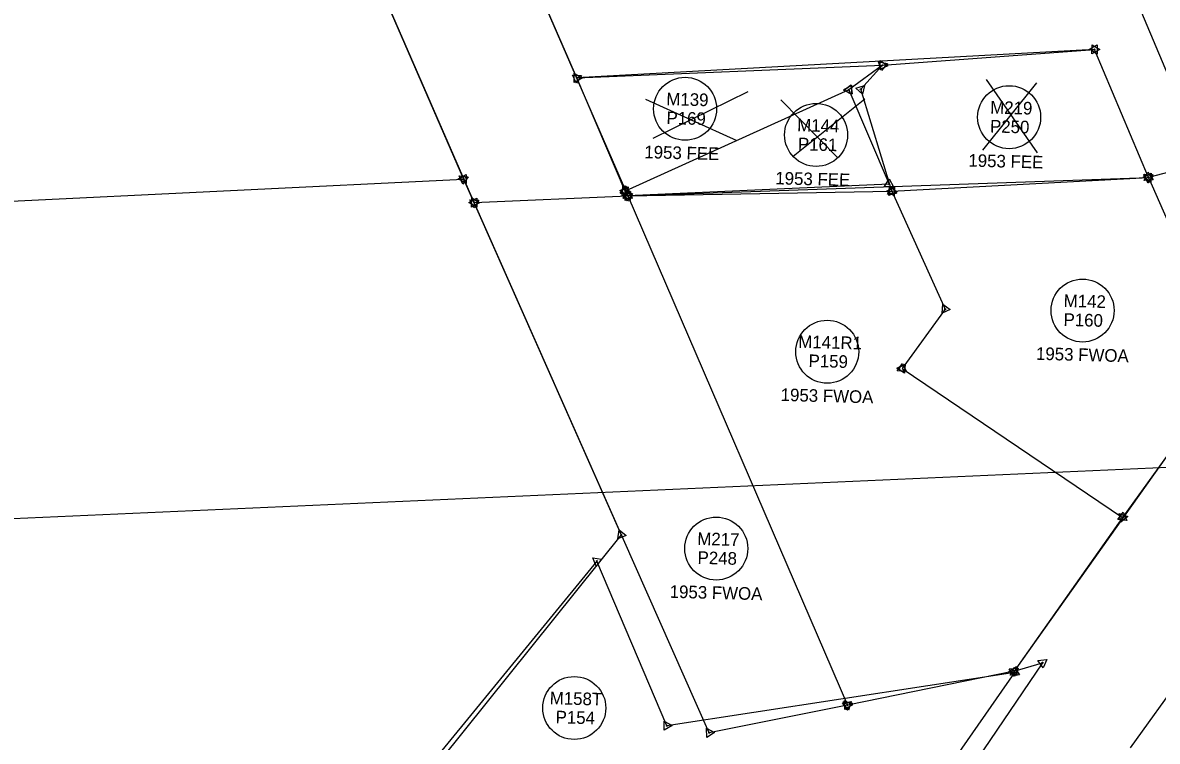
# Model space of a CAD drawing. Extents: x 325029 to 414988, y 1517527 to 1550420.
# Drawn here: x 359632.1 to 360104.7, y 1524633.6 to 1524933 of the extents above; entities that cross this region are included whole.
import ezdxf

# ---------------------------------------------------------------- set-up
doc = ezdxf.new("R2010")
doc.units = 0
for name, color, linetype in [('Level 56', 7, 'Continuous'), ('MHB', 7, 'Continuous'), ('MHBWOA', 7, 'Continuous'), ('MPL', 7, 'Continuous'), ('MRBL2', 7, 'Continuous'), ('MRBL3', 7, 'Continuous'), ('S_C', 7, 'Continuous')]:
    doc.layers.add(name, color=color, linetype=linetype)

msp = doc.modelspace()

# ---------------------------------------------------------------- linework, layer by layer
at = {"layer": 'Level 56'}
for centre in [(359908.05, 1524897.13), (360043.03, 1524893.64), (359962.61, 1524886.24), (360073.62, 1524813.08), (359967.26, 1524795.93), (359921.03, 1524713.93), (359861.9, 1524647.49)]:
    msp.add_circle(centre, 13.12, dxfattribs=at)
at = {"layer": 'MHB'}
for p, q in [((359634.08, 1525285.22), (359815.77, 1524867.87)), ((359820.21, 1524858.06), (359634.08, 1525285.22)), ((359772.67, 1525117.2), (359884.14, 1524860.9)), ((359990.32, 1524915.25), (360078.61, 1524921.86)), ((359862.94, 1524910), (359990.32, 1524915.25)), ((359990.32, 1524915.25), (359976.28, 1524905.02)), ((359981.27, 1524905.25), (359990.32, 1524915.25)), ((359883.05, 1524862.85), (359862.94, 1524910)), ((359976.28, 1524905.02), (359883.05, 1524862.85)), ((359976.28, 1524905.02), (359993.04, 1524865.73)), ((359994.17, 1524862.78), (359981.27, 1524905.25)), ((359993.04, 1524865.73), (359884.14, 1524860.9)), ((359884.14, 1524860.9), (359883.05, 1524862.85))]:
    msp.add_line(p, q, dxfattribs=at)
for points in [[(360076.43, 1524921.91), (360079.75, 1524923.72)], [(360079.65, 1524919.94), (360076.43, 1524921.91)], [(360079.75, 1524923.72), (360079.65, 1524919.94)], [(359988.66, 1524916.67), (359992.37, 1524915.97)], [(359989.91, 1524913.11), (359988.66, 1524916.67)], [(359989.1, 1524913.44), (359989.36, 1524917.21)], [(359989.36, 1524917.21), (359992.5, 1524915.1)], [(359992.5, 1524915.1), (359989.1, 1524913.44)], [(359992.37, 1524915.97), (359989.91, 1524913.11)], [(359862.86, 1524907.82), (359861.1, 1524911.17)], [(359861.1, 1524911.17), (359864.88, 1524911.02)], [(359864.88, 1524911.02), (359862.86, 1524907.82)], [(359974.09, 1524905.02), (359977.36, 1524906.92)], [(359974.12, 1524904.69), (359977.07, 1524907.05)], [(359977.07, 1524907.05), (359977.64, 1524903.32)], [(359977.36, 1524906.92), (359977.37, 1524903.14)], [(359977.37, 1524903.14), (359974.09, 1524905.02)], [(359977.64, 1524903.32), (359974.12, 1524904.69)], [(359979.15, 1524905.72), (359982.75, 1524906.85)], [(359981.93, 1524903.16), (359979.15, 1524905.72)], [(359982.75, 1524906.85), (359981.93, 1524903.16)], [(359814.01, 1524869.17), (359817.76, 1524868.74)], [(359815.52, 1524865.7), (359814.01, 1524869.17)], [(360099.07, 1524869.51), (360102.85, 1524869.71)], [(360101.13, 1524866.34), (360099.07, 1524869.51)], [(360099.28, 1524869.84), (360103.03, 1524869.36)], [(360100.74, 1524866.35), (360099.28, 1524869.84)], [(360103.03, 1524869.36), (360100.74, 1524866.35)], [(360102.85, 1524869.71), (360101.13, 1524866.34)], [(359817.76, 1524868.74), (359815.52, 1524865.7)], [(359880.88, 1524863.07), (359884.33, 1524864.62)], [(359881.05, 1524861.99), (359883.32, 1524865.02)], [(359881.15, 1524861.79), (359883.09, 1524865.03)], [(359881.78, 1524861.07), (359882.16, 1524864.83)], [(359882.16, 1524864.83), (359885.23, 1524862.63)], [(359883.09, 1524865.03), (359884.93, 1524861.73)], [(359883.32, 1524865.02), (359884.8, 1524861.54)], [(359884.33, 1524864.62), (359883.95, 1524860.87)], [(359991.1, 1524864.71), (359993.12, 1524867.91)], [(359994.88, 1524864.57), (359991.1, 1524864.71)], [(359992.92, 1524860.99), (359993.25, 1524864.76)], [(359993.12, 1524867.91), (359994.88, 1524864.57)], [(359993.25, 1524864.76), (359996.34, 1524862.59)], [(359819.05, 1524856.21), (359819.18, 1524859.99)], [(359819.18, 1524859.99), (359822.39, 1524857.99)], [(359883.95, 1524860.87), (359880.88, 1524863.07)], [(359884.8, 1524861.54), (359881.05, 1524861.99)], [(359884.93, 1524861.73), (359881.15, 1524861.79)], [(359885.23, 1524862.63), (359881.78, 1524861.07)], [(359882.21, 1524859.87), (359884.22, 1524863.08)], [(359885.99, 1524859.74), (359882.21, 1524859.87)], [(359883.08, 1524858.99), (359883.03, 1524862.77)], [(359883.03, 1524862.77), (359886.33, 1524860.93)], [(359886.33, 1524860.93), (359883.08, 1524858.99)], [(359884.22, 1524863.08), (359885.99, 1524859.74)], [(359996.34, 1524862.59), (359992.92, 1524860.99)], [(359822.39, 1524857.99), (359819.05, 1524856.21)]]:
    msp.add_lwpolyline(points, dxfattribs=at)
for centre, radius in [((360078.61, 1524921.86), 0.227), ((359990.32, 1524915.25), 0.227), ((359990.32, 1524915.25), 0.227), ((359862.94, 1524910), 0.227), ((359976.28, 1524905.02), 0.227), ((359976.28, 1524905.02), 0.227), ((359981.27, 1524905.25), 0.227), ((360101.02, 1524868.52), 1.09), ((360101.02, 1524868.52), 1.09), ((359815.77, 1524867.87), 1.09), ((359993.04, 1524865.73), 0.227), ((359883.05, 1524862.85), 1.09), ((359883.05, 1524862.85), 1.09), ((359883.06, 1524862.85), 1.09), ((359883.05, 1524862.85), 1.09), ((359884.14, 1524860.9), 0.227), ((359884.14, 1524860.9), 0.227), ((359994.17, 1524862.78), 0.227), ((359820.21, 1524858.06), 0.227)]:
    msp.add_circle(centre, radius, dxfattribs=at)
at = {"layer": 'MHBWOA'}
for p, q in [((360078.61, 1524921.86), (359862.94, 1524910)), ((360205.18, 1524888.53), (360045.08, 1524662.84)), ((360093.54, 1524630.95), (360281.17, 1524891.53)), ((360150.76, 1524881.6), (360101.02, 1524868.52)), ((359186.52, 1524836.94), (359815.77, 1524867.87)), ((359815.77, 1524867.87), (359881.4, 1524719.64)), ((359994.17, 1524862.78), (360101.02, 1524868.52)), ((360101.02, 1524868.52), (360135.53, 1524789.97)), ((359884.14, 1524860.9), (359994.17, 1524862.78)), ((359884.14, 1524860.9), (359975.64, 1524648.74)), ((359994.17, 1524862.78), (360016.36, 1524813.71)), ((359918.1, 1524637.18), (359820.21, 1524858.06)), ((360016.36, 1524813.71), (359998.45, 1524788.89)), ((359998.45, 1524788.89), (360090.29, 1524726.9)), ((360135.53, 1524789.97), (360090.29, 1524726.9)), ((360090.29, 1524726.9), (360045.08, 1524662.84)), ((359881.4, 1524719.64), (359806.47, 1524626.22)), ((359871.28, 1524708.7), (359802.97, 1524625.17)), ((359900.46, 1524640.1), (359871.28, 1524708.7)), ((360056.94, 1524666.37), (360029.7, 1524626.12)), ((360045.08, 1524662.84), (360056.94, 1524666.37)), ((360045.37, 1524662.31), (359900.46, 1524640.1)), ((360045.08, 1524662.84), (359975.64, 1524648.74)), ((360017.95, 1524622.91), (360045.37, 1524662.31)), ((359975.64, 1524648.74), (359918.1, 1524637.18))]:
    msp.add_line(p, q, dxfattribs=at)
for points in [[(359813.58, 1524867.93), (359816.91, 1524869.72)], [(359816.91, 1524869.72), (359816.8, 1524865.95)], [(360098.84, 1524868.58), (360102.16, 1524870.37)], [(360099.21, 1524867.29), (360100.85, 1524870.7)], [(360100.85, 1524870.7), (360102.98, 1524867.57)], [(360102.16, 1524870.37), (360102.05, 1524866.6)], [(359816.8, 1524865.95), (359813.58, 1524867.93)], [(359991.99, 1524862.86), (359995.33, 1524864.62)], [(359992.34, 1524861.58), (359994.05, 1524864.95)], [(359994.05, 1524864.95), (359996.11, 1524861.79)], [(359995.33, 1524864.62), (359995.18, 1524860.84)], [(360102.05, 1524866.6), (360098.84, 1524868.58)], [(360102.98, 1524867.57), (360099.21, 1524867.29)], [(359881.96, 1524860.97), (359885.3, 1524862.74)], [(359885.16, 1524858.97), (359881.96, 1524860.97)], [(359884.04, 1524858.71), (359882.31, 1524862.08)], [(359882.31, 1524862.08), (359886.09, 1524861.89)], [(359886.09, 1524861.89), (359884.04, 1524858.71)], [(359885.3, 1524862.74), (359885.16, 1524858.97)], [(359995.18, 1524860.84), (359991.99, 1524862.86)], [(359996.11, 1524861.79), (359992.34, 1524861.58)], [(359820.14, 1524855.88), (359818.35, 1524859.2)], [(359818.35, 1524859.2), (359822.13, 1524859.09)], [(359822.13, 1524859.09), (359820.14, 1524855.88)], [(360015.09, 1524811.94), (360015.47, 1524815.7)], [(360018.53, 1524813.49), (360015.09, 1524811.94)], [(360015.47, 1524815.7), (360018.53, 1524813.49)], [(359996.27, 1524789.04), (359999.67, 1524790.7)], [(359999.4, 1524786.93), (359996.27, 1524789.04)], [(359996.45, 1524788), (359998.67, 1524791.07)], [(359998.67, 1524791.07), (360000.21, 1524787.62)], [(359999.67, 1524790.7), (359999.4, 1524786.93)], [(360000.21, 1524787.62), (359996.45, 1524788)], [(360088.3, 1524726.01), (360090.5, 1524729.08)], [(360088.87, 1524728.57), (360092.43, 1524727.3)], [(360089.55, 1524724.85), (360088.87, 1524728.57)], [(360092.43, 1524727.3), (360089.55, 1524724.85)], [(360090.5, 1524729.08), (360092.06, 1524725.63)], [(360092.06, 1524725.63), (360088.3, 1524726.01)], [(359880.07, 1524717.9), (359880.56, 1524721.65)], [(359883.56, 1524719.35), (359880.07, 1524717.9)], [(359880.56, 1524721.65), (359883.56, 1524719.35)], [(359870.97, 1524706.55), (359869.56, 1524710.05)], [(359869.56, 1524710.05), (359873.3, 1524709.52)], [(359873.3, 1524709.52), (359870.97, 1524706.55)], [(360054.94, 1524667.24), (360058.69, 1524667.65)], [(360057.17, 1524664.2), (360054.94, 1524667.24)], [(360058.69, 1524667.65), (360057.17, 1524664.2)], [(360042.9, 1524662.72), (360046.07, 1524664.79)], [(360046.27, 1524661.01), (360042.9, 1524662.72)], [(360043.09, 1524663.74), (360046.85, 1524664.11)], [(360045.29, 1524660.66), (360043.09, 1524663.74)], [(360043.52, 1524661.15), (360045.3, 1524664.49)], [(360047.3, 1524661.28), (360043.52, 1524661.15)], [(360046.85, 1524664.11), (360045.29, 1524660.66)], [(360045.3, 1524664.49), (360047.3, 1524661.28)], [(360046.07, 1524664.79), (360046.27, 1524661.01)], [(359973.57, 1524649.44), (359977.28, 1524650.19)], [(359976.07, 1524646.61), (359973.57, 1524649.44)], [(359973.89, 1524650.05), (359977.64, 1524649.61)], [(359975.38, 1524646.58), (359973.89, 1524650.05)], [(359974.63, 1524646.81), (359974.47, 1524650.59)], [(359974.47, 1524650.59), (359977.82, 1524648.84)], [(359977.82, 1524648.84), (359974.63, 1524646.81)], [(359977.64, 1524649.61), (359975.38, 1524646.58)], [(359977.28, 1524650.19), (359976.07, 1524646.61)], [(359899.4, 1524638.2), (359899.34, 1524641.98)], [(359899.34, 1524641.98), (359902.64, 1524640.14)], [(359902.64, 1524640.14), (359899.4, 1524638.2)], [(359917.09, 1524635.25), (359916.92, 1524639.02)], [(359916.92, 1524639.02), (359920.28, 1524637.28)], [(359920.28, 1524637.28), (359917.09, 1524635.25)]]:
    msp.add_lwpolyline(points, dxfattribs=at)
for centre, radius in [((359815.77, 1524867.87), 0.227), ((360101.02, 1524868.52), 0.227), ((360101.02, 1524868.52), 0.227), ((359884.14, 1524860.9), 0.227), ((359884.14, 1524860.9), 0.227), ((359994.17, 1524862.78), 1.09), ((359994.17, 1524862.78), 0.227), ((359820.21, 1524858.06), 0.227), ((360016.36, 1524813.71), 0.227), ((359998.45, 1524788.89), 1.09), ((359998.45, 1524788.89), 1.09), ((360090.29, 1524726.9), 1.09), ((360090.29, 1524726.9), 0.227), ((359881.4, 1524719.64), 0.227), ((359871.28, 1524708.7), 0.227), ((360056.94, 1524666.37), 0.227), ((360045.08, 1524662.84), 0.227), ((360045.08, 1524662.84), 0.227), ((360045.37, 1524662.31), 0.227), ((359975.64, 1524648.74), 1.09), ((359975.64, 1524648.74), 1.09), ((359975.64, 1524648.74), 0.227), ((359900.46, 1524640.1), 0.227), ((359918.1, 1524637.18), 0.227)]:
    msp.add_circle(centre, radius, dxfattribs=at)
at = {"layer": 'MPL'}
for p, q in [((359862.94, 1524910), (359772.67, 1525117.2)), ((360101.02, 1524868.52), (360078.61, 1524921.86)), ((359815.77, 1524867.87), (359820.21, 1524858.06)), ((359884.14, 1524860.9), (360101.02, 1524868.52)), ((359820.21, 1524858.06), (359884.14, 1524860.9))]:
    msp.add_line(p, q, dxfattribs=at)
for points in [[(360077.46, 1524920.01), (360077.59, 1524923.79)], [(360080.8, 1524921.79), (360077.46, 1524920.01)], [(360077.59, 1524923.79), (360080.8, 1524921.79)], [(359861.8, 1524908.15), (359861.91, 1524911.93)], [(359861.91, 1524911.93), (359865.13, 1524909.94)], [(359865.13, 1524909.94), (359861.8, 1524908.15)], [(359813.58, 1524867.92), (359816.9, 1524869.73)], [(359816.9, 1524869.73), (359816.81, 1524865.95)], [(360100.92, 1524866.34), (360099.18, 1524869.69)], [(360099.18, 1524869.69), (360102.96, 1524869.52)], [(360102.96, 1524869.52), (360100.92, 1524866.34)], [(359816.81, 1524865.95), (359813.58, 1524867.92)], [(359818.02, 1524858.11), (359821.35, 1524859.91)], [(359821.35, 1524859.91), (359821.24, 1524856.14)], [(359882.3, 1524859.73), (359884.06, 1524863.07)], [(359886.07, 1524859.88), (359882.3, 1524859.73)], [(359884.06, 1524863.07), (359886.07, 1524859.88)], [(359821.24, 1524856.14), (359818.02, 1524858.11)]]:
    msp.add_lwpolyline(points, dxfattribs=at)
for centre in [(360078.61, 1524921.86), (359862.94, 1524910), (359815.77, 1524867.87), (360101.02, 1524868.52), (359884.14, 1524860.9), (359820.21, 1524858.06)]:
    msp.add_circle(centre, 0.227, dxfattribs=at)
at = {"layer": 'MRBL2'}
msp.add_line((357681.26, 1524640), (360124.37, 1524748.44), dxfattribs=at)
at = {"layer": 'MRBL3'}
msp.add_line((359995.71, 1525182.03), (360154.03, 1524803.87), dxfattribs=at)
at = {"layer": 'S_C'}
for p, q in [((360054.4, 1524908), (360031.95, 1524879.91)), ((360033.42, 1524909.38), (360054.69, 1524878.81)), ((359934.19, 1524904.25), (359894.62, 1524884.8)), ((359891.57, 1524901.18), (359929.67, 1524883.94)), ((359947.87, 1524900.9), (359971.64, 1524876.72)), ((359982.87, 1524901.13), (359953.09, 1524877.21))]:
    msp.add_line(p, q, dxfattribs=at)

# ---------------------------------------------------------------- texts
at = {"layer": 'Level 56'}
for s, p in [('M139', (359900.19, 1524898.65)), ('M219', (360035.08, 1524895.16)), ('P169', (359900.24, 1524890.78)), ('M144', (359954.68, 1524887.77)), ('P250', (360035.01, 1524887.28)), ('P161', (359955, 1524879.88)), ('1953 FEE', (359891.02, 1524876.56)), ('1953 FEE', (360026, 1524873.06)), ('1953 FEE', (359945.58, 1524865.67)), ('M142', (360065.69, 1524814.6)), ('P160', (360065.63, 1524806.72)), ('M141R1', (359955.15, 1524797.56)), ('P159', (359959.42, 1524789.57)), ('1953 FWOA', (360054.16, 1524792.57)), ('1953 FWOA', (359947.8, 1524775.42)), ('M217', (359913.1, 1524715.45)), ('P248', (359913.19, 1524707.57)), ('1953 FWOA', (359901.58, 1524693.42)), ('M158T', (359851.62, 1524649.08)), ('P154', (359854.07, 1524641.13))]:
    msp.add_text(s, height=5.249, rotation=358.4907, dxfattribs=at).set_placement(p)

doc.saveas('drawing.dxf')
